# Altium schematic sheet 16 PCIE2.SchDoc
size 297 x 209 mm
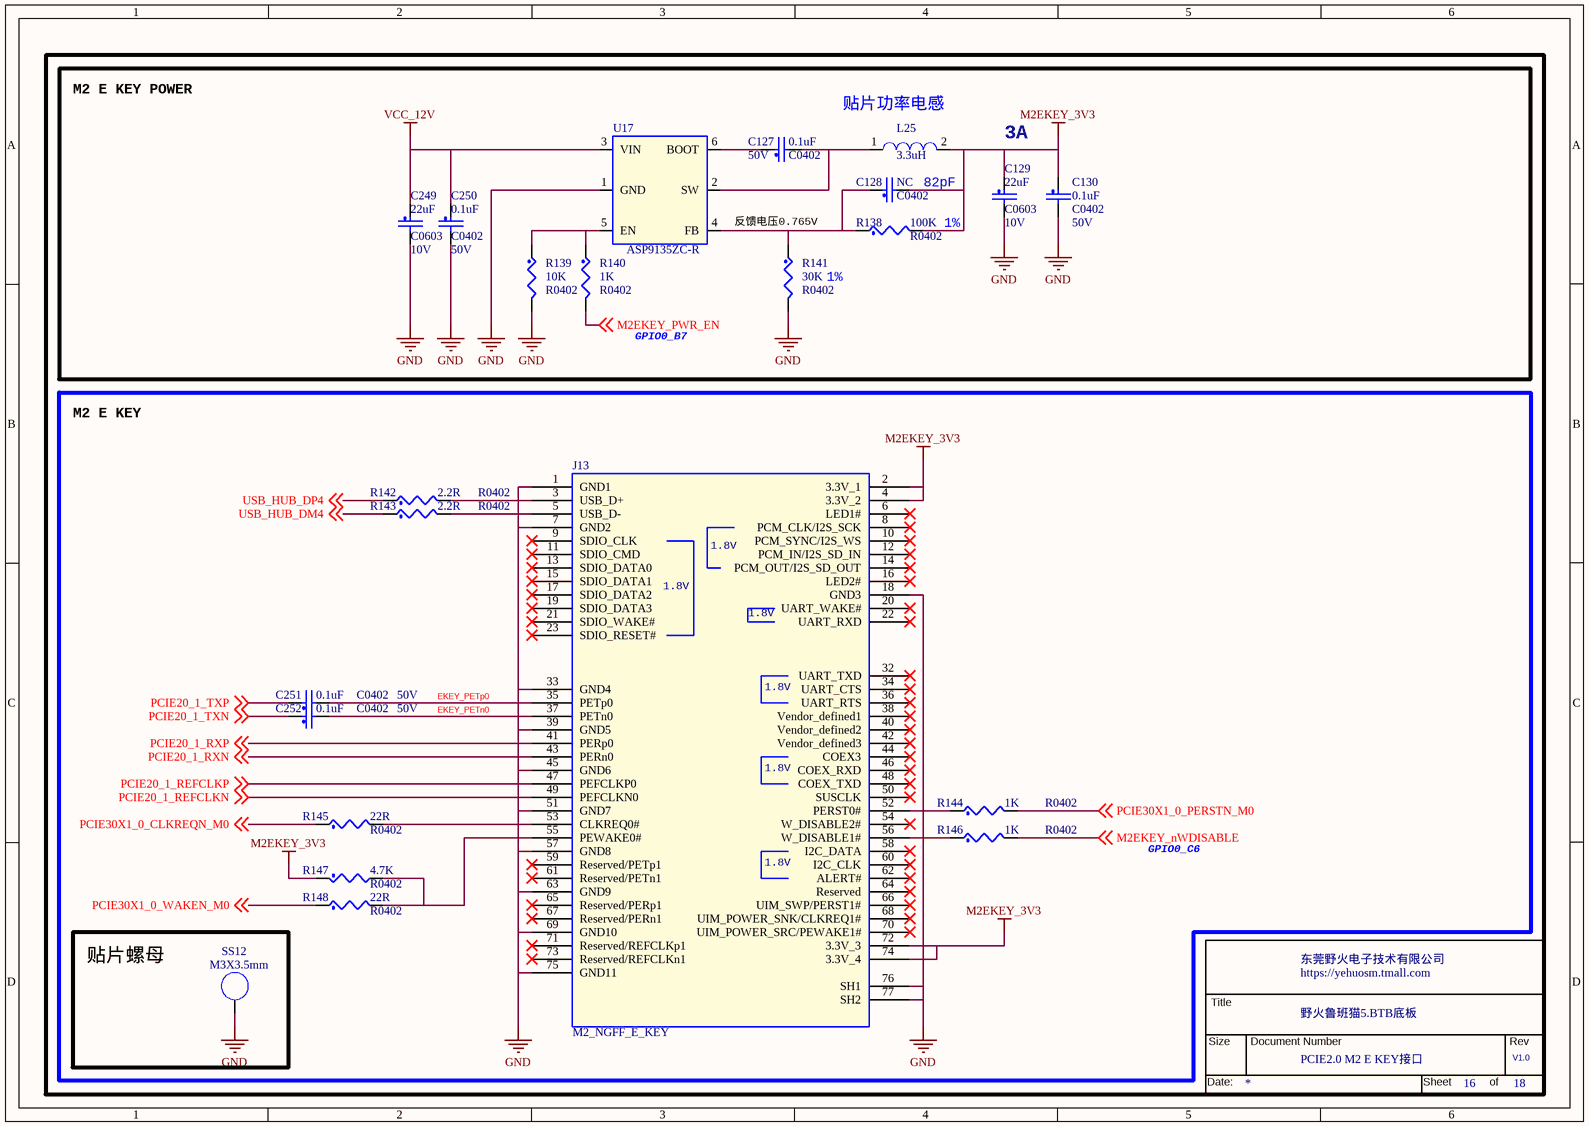
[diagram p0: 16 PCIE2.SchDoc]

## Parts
*  Doc: PCIE2.0 M2 E KEY接口  RevCode: V1.0  Title: 野火鲁班猫5.BTB底板  OrgName: 东莞野火电子技术有限公司  Page Number: 16  Page Count: 18  (hidden comment: TitleBlock_YHSCH)  (graphical)
C127  0.1uF  Voltage: 50V  [C0402]
C128  NC  [C0402]
C129  22uF  Voltage: 10V  [C0603]
C130  0.1uF  Voltage: 50V  [C0402]
C249  22uF  Voltage: 10V  [C0603]
C250  0.1uF  Voltage: 50V  [C0402]
C251  0.1uF  Voltage: 50V  [C0402]
C252  0.1uF  Voltage: 50V  [C0402]
J13  M2_NGFF_E_KEY  [M2_NGFF_E_KEY]
L25  3.3uH  [l4520]
R138  100K  [R0402]
R139  10K  [R0402]
R140  1K  [R0402]
R141  30K  [R0402]
R142  2.2R  [R0402]
R143  2.2R  [R0402]
R144  1K  [R0402]
R145  22R  [R0402]
R146  1K  [R0402]
R147  4.7K  [R0402]
R148  22R  [R0402]
SS12  M3X3.5mm  [smtso-m3]
U17  ASP9135ZC-R  [SOT23_6]

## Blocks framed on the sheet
3A: C127-C130 C249 C250 L25 R138-R141 U17
M2 E KEY: C251 C252 J13 R142-R148
贴片螺母: SS12

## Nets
GND: C129.2 C130.2 C249.2 C250.2 J13.1(GND1) J13.7(GND2) J13.18(GND3) J13.33(GND4) J13.39(GND5) J13.45(GND6) J13.51(GND7) J13.57(GND8) J13.63(GND9) J13.69(GND10) J13.75(GND11) J13.76(SH1) J13.77(SH2) R139.2 R141.2 SS12.1(NC_1) U17.1(GND)
M2EKEY_3V3: C128.2 C129.1 C130.1 J13.2(3.3V_1) J13.4(3.3V_2) J13.72(3.3V_3) J13.74(3.3V_4) L25.2 R138.2 R147.1
VCC_12V: C249.1 C250.1 U17.3(VIN)
EKEY_PETn0: C252.2 J13.37(PETn0)
EKEY_PETp0: C251.2 J13.35(PETp0)
M2EKEY_nWDISABLE: R146.2 ; off-sheet M2EKEY_nWDISABLE
M2EKEY_PWR_EN: R140.2 ; off-sheet M2EKEY_PWR_EN
PCIE20_1_REFCLKN: J13.49(PEFCLKN0) ; off-sheet PCIE20_1_REFCLKN
PCIE20_1_REFCLKP: J13.47(PEFCLKP0) ; off-sheet PCIE20_1_REFCLKP
PCIE20_1_RXN: J13.43(PERn0) ; off-sheet PCIE20_1_RXN
PCIE20_1_RXP: J13.41(PERp0) ; off-sheet PCIE20_1_RXP
PCIE20_1_TXN: C252.1 ; off-sheet PCIE20_1_TXN
PCIE20_1_TXP: C251.1 ; off-sheet PCIE20_1_TXP
PCIE30X1_0_CLKREQN_M0: R145.1 ; off-sheet PCIE30X1_0_CLKREQN_M0
PCIE30X1_0_PERSTN_M0: R144.2 ; off-sheet PCIE30X1_0_PERSTN_M0
PCIE30X1_0_WAKEN_M0: R148.1 ; off-sheet PCIE30X1_0_WAKEN_M0
USB_HUB_DM4: R143.1 ; off-sheet USB_HUB_DM4
USB_HUB_DP4: R142.1 ; off-sheet USB_HUB_DP4
NetC127_1: C127.1 U17.6(BOOT)
NetC127_2: C127.2 L25.1 U17.2(SW)
NetC128_1: C128.1 R138.1 R141.1 U17.4(FB)
NetJ13_3: J13.3(USB_D+) R142.2
NetJ13_5: J13.5(USB_D-) R143.2
NetJ13_52: J13.52(PERST0#) R144.1
NetJ13_53: J13.53(CLKREQ0#) R145.2
NetJ13_55: J13.55(PEWAKE0#) R147.2 R148.2
NetJ13_56: J13.56(W_DISABLE1#) R146.1
NetR139_1: R139.1 R140.1 U17.5(EN)

Not connected (* = marked no-connect by the designer): J13 6(LED1#)* 8(PCM_CLK/I2S_SCK)* 9(SDIO_CLK)* 10(PCM_SYNC/I2S_WS)* 11(SDIO_CMD)* 12(PCM_IN/I2S_SD_IN)* 13(SDIO_DATA0)* 14(PCM_OUT/I2S_SD_OUT)* 15(SDIO_DATA1)* 16(LED2#)* 17(SDIO_DATA2)* 19(SDIO_DATA3)* 20(UART_WAKE#)* 21(SDIO_WAKE#)* 22(UART_RXD)* 23(SDIO_RESET#)* 32(UART_TXD)* 34(UART_CTS)* 36(UART_RTS)* 38(Vendor_defined1)* 40(Vendor_defined2)* 42(Vendor_defined3)* 44(COEX3)* 46(COEX_RXD)* 48(COEX_TXD)* 50(SUSCLK)* 54(W_DISABLE2#)* 58(I2C_DATA)* 59(Reserved/PETp1)* 60(I2C_CLK)* 61(Reserved/PETn1)* 62(ALERT#)* 64(Reserved)* 65(Reserved/PERp1)* 66(UIM_SWP/PERST1#)* 67(Reserved/PERn1)* 68(UIM_POWER_SNK/CLKREQ1#)* 70(UIM_POWER_SRC/PEWAKE1#)* 71(Reserved/REFCLKp1)* 73(Reserved/REFCLKn1)*

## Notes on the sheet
- M2 E KEY POWER
- (near L25) 贴片功率电感
- 82pF
- 反馈电压0.765V
- 1%
- GPIO0_B7
- GPIO0_C6

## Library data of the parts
* = TitleBlock_YHSCH: Cage Code: 1
C127 C251 C252 = CAP_NP: CLASS: DISCRETE; 规格: 贴片电容0.1uF 10% 50V X5R 0402; 规格编号: 0402X104K500NT; 条码: EBF29060118; 品牌: 风华; 类别: 贴片电容0402; 规格书: 风华电容.pdf; 价格: 0.029826; 生命周期: 量产
C128 = CAP_NP: CLASS: DISCRETE; 类别: 贴片电容0402; 条码: EBF29060149; 规格: 贴片电容NC 预留
C129 C249 = CAP_NP: CLASS: DISCRETE; 规格: 贴片电容22uF 20% 10V X5R 0603; 规格编号: CL10A226MP8NUNE; 条码: EBF29060163; 品牌: 三星; 类别: 贴片电容0603; 规格书: 三星电容.pdf; 价格: 0.078818; 生命周期: 量产
C130 C250 = CAP_NP: CLASS: DISCRETE; 生命周期: 量产; 价格: 0.029826; 规格书: 风华电容.pdf; 类别: 贴片电容0402; 品牌: 风华; 条码: EBF29060118; 规格编号: 0402X104K500NT; 规格: 贴片电容0.1uF 10% 50V X5R 0402
J13 = M2_NGFF_E_KEY: 规格: M.2 NGFF 高度5.5MM M.2 E KEY连接器 75PIN; 规格编号: APCI0317-P001A; 条码: EBFCIS230525165441; 品牌: LOTES; 类别: 金手指连接器; 规格书: LOTES_APCI0317-P001A.pdf; 生命周期: 量产; 备注: RK3588 LBC5 M2无线网卡连接器
L25 = IND: CLASS: DISCRETE; 价格: 1.5992; 规格编号: TMPC0402HP-3R3MG-Z02; 生命周期: 量产; 规格书: 台庆-功率电感.pdf; 类别: 贴片电感0402; 品牌: 台庆; 条码: EBF29050040; 规格: 贴片电感3.3uH ±20% 3A 直流电阻69mΩ
R138 = RES: CLASS: DISCRETE; 生命周期: 量产; 规格书: 合科泰-RI系列电阻.pdf; 类别: 贴片电阻0402; 品牌: 合科泰; 条码: EBF29070054; 规格编号: RI0402L1003FT; 规格: 贴片电阻100K 1% 1/16W 0402
R139 = RES: CLASS: DISCRETE; 规格: 贴片电阻10K 1% 1/16W 0402; 规格编号: 0402WGF1002TCE; 条码: EBF29070046; 品牌: 厚声; 类别: 贴片电阻0402; 规格书: 厚声-无铅厚膜电阻.pdf; 价格: 0.002773; 生命周期: 量产
R140 R144 R146 = RES: CLASS: DISCRETE; 生命周期: 量产; 规格书: 合科泰-RI系列电阻.pdf; 类别: 贴片电阻0402; 品牌: 合科泰; 条码: EBF29070050; 规格编号: RI0402L1001FT; 规格: 贴片电阻1K 1% 1/16W 0402
R141 = RES: CLASS: DISCRETE; 规格: 贴片电阻30K 1% 1/16W 0402; 规格编号: RI0402L3002FT; 条码: EBF29070048; 品牌: 合科泰; 类别: 贴片电阻0402; 规格书: 合科泰-RI系列电阻.pdf; 生命周期: 量产
R142 = RES: CLASS: DISCRETE; 生命周期: 量产; 价格: 0.003072; 规格书: 厚声-无铅厚膜电阻.pdf; 类别: 贴片电阻0402; 品牌: 厚声; 条码: EBF29070280; 规格编号: 0402WGF220KTCE; 规格: 贴片电阻2.2R 1% 1/16W 0402
R143 = RES: CLASS: DISCRETE; 规格: 贴片电阻2.2R 1% 1/16W 0402; 规格编号: 0402WGF220KTCE; 条码: EBF29070280; 品牌: 厚声; 类别: 贴片电阻0402; 规格书: 厚声-无铅厚膜电阻.pdf; 价格: 0.003072; 生命周期: 量产
R145 R148 = RES: CLASS: DISCRETE; 规格: 贴片电阻22R 1% 1/16W 0402; 规格编号: RI0402L22R0FT; 条码: EBF29070181; 品牌: 合科泰; 类别: 贴片电阻0402; 规格书: 合科泰-RI系列电阻.pdf; 生命周期: 量产
R147 = RES: CLASS: DISCRETE; 规格: 贴片电阻4.7K 1% 1/16W 0402; 规格编号: RI0402L4701FT; 条码: EBF29070047; 品牌: 合科泰; 类别: 贴片电阻0402; 规格书: 合科泰-RI系列电阻.pdf; 生命周期: 量产
SS12 = SPACER: CLASS: IC; 规格: SMT贴片螺母M3 台阶高度1.53mm 台阶外径：4.09mm 螺柱长度：3.5MM; 规格编号: SMTSO3035CTJ; 条码: EBF29410007; 品牌: 雄和远景; 类别: 贴片螺母; 规格书: Sinhoo电路板表贴螺母柱_PCB_SMT_Nuts.pdf; 生命周期: 量产
U17 = TP6327GS6: 规格: DC-DC电源芯片 可输出电流 3A 开关工作频率 600kHz 输出类型 ADJ 输入电压范围：4V-18V; 条码: EBFCIS240710113940; 品牌: 安森德; 类别: 电源管理-DCDC; 规格书: 安森德_ASP9135ZC-R.pdf; 生命周期: 量产; 备注: RK3566金手指与BTB底板替换物料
